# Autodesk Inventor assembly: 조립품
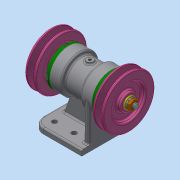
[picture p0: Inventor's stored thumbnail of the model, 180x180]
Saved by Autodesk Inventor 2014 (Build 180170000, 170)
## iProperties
Created: 2020-06
Part Number: 조립품
Document SubType Name: Assembly
Designer: kh
Author: kh
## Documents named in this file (12)
- C:\Users\kh\Desktop\700606V1044\조립품.iam
- C:\Users\kh\Desktop\700606V1044\본체.ipt
- C:\Users\kh\Desktop\700606V1044\축.ipt
- C:\Users\kh\Desktop\700606V1044\베어링 6204.ipt
- C:\Users\kh\Desktop\700606V1044\키 5x5x12.ipt
- C:\Users\kh\Desktop\700606V1044\커버.ipt
- C:\Users\kh\Desktop\700606V1044\오일 실 20 32 5.ipt
- C:\Users\kh\Desktop\700606V1044\V-벨트풀리.ipt
- C:\Users\kh\Desktop\700606V1044\평면 와셔 10x21.ipt
- C:\Users\kh\Desktop\700606V1044\스프링 와셔 10.ipt
- C:\Users\kh\Desktop\700606V1044\너트 M10.ipt
- C:\Users\kh\Desktop\700606V1044\볼트 M4.ipt
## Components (2 placed, 1 different names)
1. V-벨트풀리:1 — Mate:23, Mate:24, Mate:25, Mate:30
2. V-벨트풀리:2 — Mate:26, Mate:27, Mate:28, Mate:32
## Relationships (8: Mate 8)
- Mate:23: V-벨트풀리:1
- Mate:24: V-벨트풀리:1
- Mate:25: V-벨트풀리:1
- Mate:26: V-벨트풀리:2
- Mate:27: V-벨트풀리:2
- Mate:28: V-벨트풀리:2
- Mate:30: V-벨트풀리:1
- Mate:32: V-벨트풀리:2
